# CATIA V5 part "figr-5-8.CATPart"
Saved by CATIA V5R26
Part number: Part1
Bounding box of the stored display mesh (mm): x 0 to 150, y -70 to 70, z -150 to 69.804
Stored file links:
  D:\_Deepak\CATIA\CATIA V5-6R2016_Deepak\Resources\Part files\Partfiles\c05_catia_v5_6r2016_prt\figr-5-8.CATPart
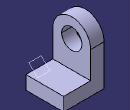
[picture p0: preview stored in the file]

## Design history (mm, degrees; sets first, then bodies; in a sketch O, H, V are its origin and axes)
Set1
  Plane1: type Angle, RefPlane face of Pad2, Direction edge of Pad2, Angle -45
Body1 (main body)
  Sketch1 on yz-plane, origin (0, 0, 0), H (0, 1, 0), V (0, 0, 1)
    arc A1 centre (0, 0) radius 70 from (70, 0) to (-70, 0) ccw
    point P1 (70, 0)
    point P2 (-70, 0)
    line L1 (-70, 0) -> (-70, -150)
    line L2 (-70, -150) -> (70, -150)
    line L3 (70, -150) -> (70, 0)
    circle A2 centre (0, 0) radius 37.5
    radius A1 = 70
    radius A2 = 37.5
    distance O L2 = 150
    coincidence: P1 H, P2 H
    tangency: L1 A1, L3 A1
    horizontal: L2 H
  Pad1: profile Sketch1, direction (1, 0, 0), length 50
  Sketch2 on face of Pad1, origin (50, 0, 0), H (0, 1, 0), V (0, 0, 1)
    line L1 (-70, -150) -> (70, -150)
    line L2 (70, -150) -> (70, -100)
    line L3 (70, -100) -> (-70, -100)
    line L4 (-70, -100) -> (-70, -150)
    reference projected line E1 (-70, -150) -> (70, -150) from edge [face of Pad1 | face of Pad1]
    reference projected line E2 (-70, 0) -> (-70, -150) from edge [face of Pad1 | face of Pad1]
    reference projected line E3 (70, -150) -> (70, 0) from edge [face of Pad1 | face of Pad1]
    length L2 = 50
    horizontal: L1 H, L3 H
    vertical: L2 V, L4 V
    coincidence: L1 E1, E2 L4, L2 E3
  Pad2: profile Sketch2, direction (1, 0, 0), length 100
